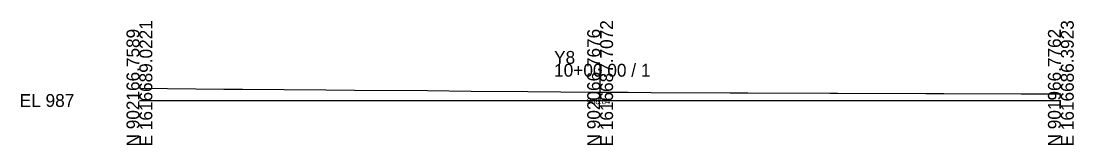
# Model space of a CAD drawing. Extents: x -26 to 1403, y -10 to 3025.
# Drawn here: x -25.7 to 202.8, y -9.7 to 17.3 of the extents above; entities that cross this region are included whole.
import ezdxf

# ---------------------------------------------------------------- set-up
doc = ezdxf.new("R2010")
doc.units = 0
for name, color, linetype in [('Exist Cross Section Cell', 7, 'Continuous'), ('Exist XS Center Line Elevation Label', 7, 'Continuous'), ('Exist XS Ground Line', 7, 'Continuous')]:
    doc.layers.add(name, color=color, linetype=linetype)

msp = doc.modelspace()

# ---------------------------------------------------------------- linework, layer by layer
at = {"layer": 'Exist Cross Section Cell'}
for p, q in [((100, 0), (100, 7.99)), ((0, 0), (100, 0)), ((100, 0), (200, 0))]:
    msp.add_line(p, q, dxfattribs=at)
at = {"layer": 'Exist XS Ground Line'}
for p, q in [((0, 2.66), (18.35, 2.49)), ((18.35, 2.49), (22.38, 2.46)), ((22.38, 2.46), (40.46, 2.32)), ((40.46, 2.32), (46.66, 2.27)), ((46.66, 2.27), (62.55, 2.15)), ((62.55, 2.15), (72.01, 2.06)), ((72.01, 2.06), (84.3, 1.96)), ((84.3, 1.96), (98.62, 1.85)), ((98.62, 1.85), (100, 1.84)), ((100, 1.84), (106.1, 1.79)), ((106.1, 1.79), (111.05, 1.77)), ((111.05, 1.77), (128.22, 1.68)), ((128.22, 1.68), (129.01, 1.67)), ((129.01, 1.67), (132.05, 1.66)), ((132.05, 1.66), (149.83, 1.59)), ((149.83, 1.59), (151.5, 1.59)), ((151.5, 1.59), (170.67, 1.52)), ((170.67, 1.52), (174.58, 1.5)), ((174.58, 1.5), (191.41, 1.46)), ((191.41, 1.46), (198.05, 1.44)), ((198.05, 1.44), (200, 1.44))]:
    msp.add_line(p, q, dxfattribs=at)

# ---------------------------------------------------------------- texts
at = {"layer": 'Exist Cross Section Cell'}
for s, p in [('E 1616689.0221', (2.8, -10)), ('E 1616687.7072', (102.8, -10)), ('E 1616686.3923', (202.8, -10)), ('N 902166.7589', (0, -10)), ('N 902066.7676', (100, -10)), ('N 901966.7762', (200, -10))]:
    msp.add_text(s, height=2.8, rotation=90, dxfattribs=at).set_placement(p)
for s, p in [('Y8', (90, 7.99)), ('10+00.00 / 1', (90, 5.19)), ('EL 987', (-26, -1.4))]:
    msp.add_text(s, height=2.8, dxfattribs=at).set_placement(p)
at = {"layer": 'Exist XS Center Line Elevation Label'}
msp.add_text('988.84', height=1.25, dxfattribs=at).set_placement((97.1, -0.79))

doc.saveas('drawing.dxf')
